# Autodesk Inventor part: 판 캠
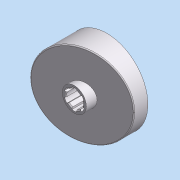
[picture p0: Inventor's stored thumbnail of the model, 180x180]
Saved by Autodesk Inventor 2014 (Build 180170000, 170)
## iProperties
Created: 2012-05
Part Number: 판 캠
Document SubType Name: 모델링
Designer: SeoGD™
Material: 강철
Appearance: 알루미늄 - 평지
Density: 7.85 g/cm^3
Mass: 681.587 g
Surface Area: 331.303 cm^2
Volume: 86.8264 cm^3
변환 표준: STEP AP214IS
파일 이름: C:\Users\SeoGD\Desktop\?쒗뿕\??stp
전처리기: Build: 253, Release: 2010 SP1 - Date: Wed 07/29/2009
전송 단위: 밀리미터
불확실성: 0.01
Author: SeoGD™
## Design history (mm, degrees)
node "작업 평면4"
sketch "스케치1"
  geometry: C1 r 44.5 at (0, 0); 1 further point
  constraints: 1 centre point, 1 coincident
  dimensions: "d25" = 89 diameter of C1
extrude "돌출1" new body sketch "스케치1" distance "d1" = 40; taper "d2" = 0 deg
sketch "스케치2"
  geometry: L1 (-44.5, 15)-(44.5, 38.847); L2 (-44.5, 0)-(-44.5, 40) reference; L3 (-44.5, 40)-(44.5, 40) reference; L4 (44.5, 0)-(44.5, 40) reference; 1 further point
  constraints: 2 end point, 2 point on line
  dimensions: "d26" = 15 distance of L2.start L1.start; "d27" = 75 deg angle of L1 L2
extrude "돌출2" cut sketch "스케치2" stored distance "d5" = 40; taper "d6" = 0 deg
node "작업 평면1"
sketch "스케치3"
  geometry: C1 r 13 at (0, 0); 1 further point
  constraints: 1 centre point, 1 coincident
  dimensions: "d9" = 26 diameter of C1
extrude "돌출3" join sketch "스케치3" distance "d10" = 38; taper "d11" = 0 deg
hole "구멍1" diameter "d14" = 18; stored, may be unused: countersink angle "d18" = 90 deg, drill point angle "d20" = 118 deg; dims "d12" = 10, "d13" = 10, "d15" = 6, "d16" = 4, "d17" = 2, "d19" = 8
feature "쉘2" dims "d29" = 5
sketch "스케치6"
  geometry: C1 r 17.5 at (0, 0); C2 r 14 at (0, 0) reference; 1 further point
  constraints: 1 centre point, 1 coincident
  dimensions: "d28" = 35 diameter of C1
extrude "돌출4" join sketch "스케치6" stored distance "d30" = 38; taper "d31" = 0 deg
fillet "모깎기1" dims "d32" = 3
chamfer "모따기1" distance "d21" = 1; stored, may be unused: second distance "d22" = 2, angle "d23" = 45 deg
sketch "스케치7"
  geometry: L1 (-12.374, 12.374)-(-27.931, 27.931); A1 r 39.5 centre (0, 0) between (-27.931, 27.931) and (0, 39.5) reference; 2 further points
  constraints: 2 end point, 2 point on circle, 1 point on line, 1 vertical alignment, 2 other
  dimensions: "d33" = 45 deg dimension on point (0, 0) L1.start A1.end
feature "리브1" sketch "스케치7" dims "d34" = 5, "d35" = 1, "d36" = 0
fillet "모깎기2" dims "d37" = 3
sketch "스케치8"
  geometry: L1 (2.5, 10.712)-(2.5, 8.646); L2 (-2.5, 10.712)-(-2.5, 8.646); A1 r 11 centre (0, 0) between (2.5, 10.712) and (-2.5, 10.712); A2 r 9 centre (0, 0) between (2.5, 8.646) and (-2.5, 8.646) reference; 1 further point
  constraints: 4 end point, 4 point on circle, 2 parallel, 1 centre point, 1 coincident, 1 vertical
  dimensions: "d41" = 22 diameter of A1; "d42" = 5 distance between parallel lines of L1 L2
extrude "돌출5" cut sketch "스케치8" stored distance "d43" = 38; taper "d44" = 0 deg
fillet "모깎기3" dims "d48" = 1
node "솔리드1"
node "솔리드 본체"
node "곡면 본체"
pattern_circular "원형 패턴1" dims angle "d39" = 360 deg
pattern_circular "원형 패턴2" dims angle "d46" = 360 deg
node "솔리드2"
